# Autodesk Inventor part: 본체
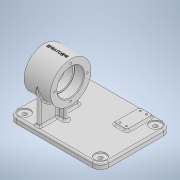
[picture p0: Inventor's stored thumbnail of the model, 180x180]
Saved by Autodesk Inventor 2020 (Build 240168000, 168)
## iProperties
Created: 2024-04
Part Number: 본체
Material: 알루미늄 6061
Document SubType Name: Modeling
Designer: oem
Density: 2.7 g/cm^3
Appearance: 알루미늄 - 평지
Mass: 650.251 g
Surface Area: 600.506 cm^2
Volume: 240.834 cm^3
Sending System: Autodesk Inventor 2025
Preprocessor: ST-DEVELOPER v20
Author: jhkim
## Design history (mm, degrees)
feature "솔리드1"
node "솔리드2"
